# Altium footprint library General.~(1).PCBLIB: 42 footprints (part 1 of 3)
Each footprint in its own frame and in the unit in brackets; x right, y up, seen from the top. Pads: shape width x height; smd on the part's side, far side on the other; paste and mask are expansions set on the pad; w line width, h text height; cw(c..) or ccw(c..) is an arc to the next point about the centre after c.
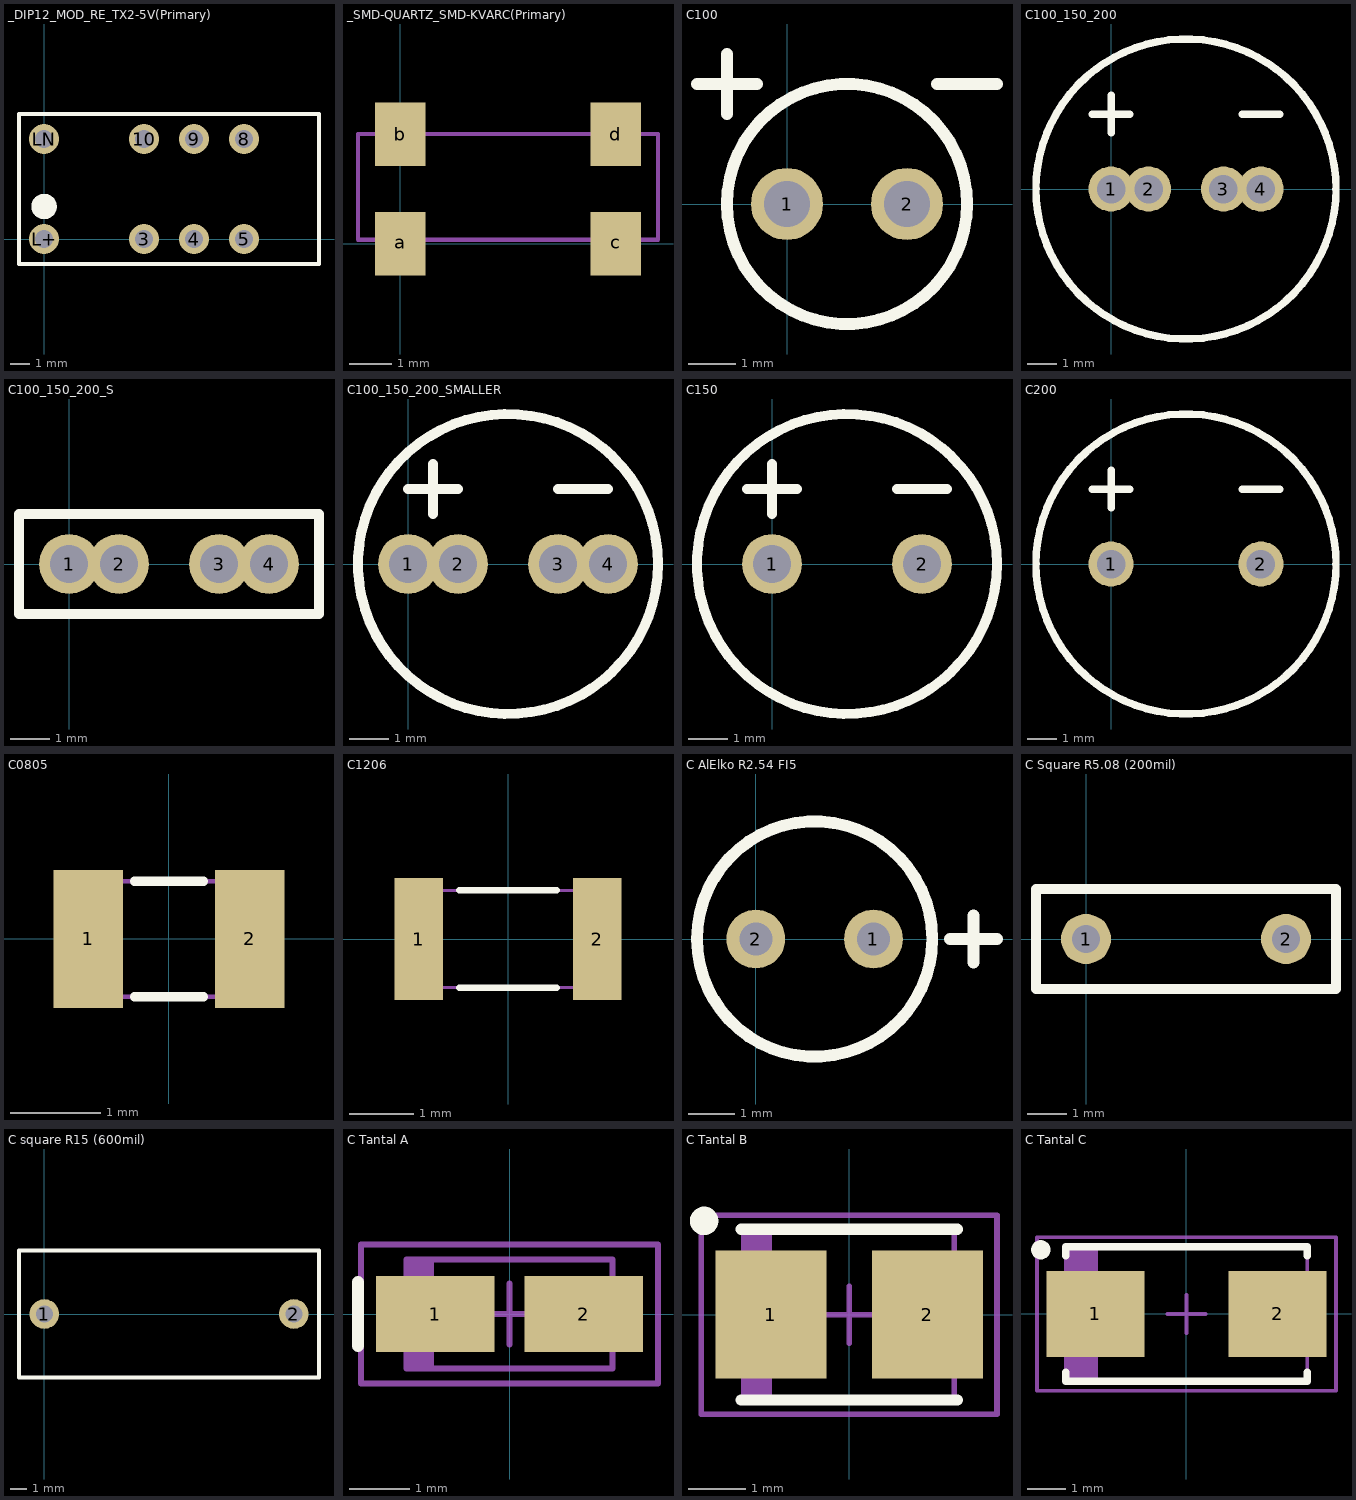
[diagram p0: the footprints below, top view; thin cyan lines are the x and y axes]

## _DIP12_MOD_RE_TX2-5V(Primary) [mil]
pads (8):
  round 60 hole 36: 3(200,0) 4(300,0) 5(400,0) 8(400,200) 9(300,200) 10(200,200) L+(0,0) LN(0,200)
Top Overlay:
  circle w25: c0,65 r13
  lines w8: -50,-50 -50,250 550,250 550,-50 -50,-50

## _SMD-QUARTZ_SMD-KVARC(Primary) [mm]
pads (4):
  rect 1.2x1.5 smd: a(0,0) b(0,2.6) c(5.1,0) d(5.1,2.6)
Mechanical 1:
  lines w0.1: -1,0.1 6.1,0.1 6.1,2.6 -1,2.6 -1,0.1

## C100 [mil]
pads (2):
  round 60 hole 38: 1(0,0) 2(100,0)
Top Overlay:
  circle w10: c50,0 r100
  lines w10: -75,100 -25,100 ; -50,75 -50,125 ; 125,100 175,100

## C100_150_200 [mil]
pads (4):
  round 60 hole 38: 1(0,0) 2(50,0) 3(150,0) 4(200,0)
Top Overlay:
  circle w10: c100,0 r200
  lines w10: -25,100 25,100 ; 0,75 0,125 ; 175,100 225,100

## C100_150_200_S [mil]
pads (4):
  round 60 hole 38: 1(0,0) 2(50,0) 3(150,0) 4(200,0)
Top Overlay:
  lines w10: -50,-50 -50,50 250,50 250,-50 -50,-50

## C100_150_200_SMALLER [mil]
pads (4):
  round 60 hole 38: 1(0,0) 2(50,0) 3(150,0) 4(200,0)
Top Overlay:
  circle w10: c100,0 r150
  lines w10: 0,75 50,75 ; 25,50 25,100 ; 150,75 200,75

## C150 [mil]
pads (2):
  round 60 hole 38: 1(0,0) 2(150,0)
Top Overlay:
  circle w10: c75,0 r150
  lines w10: -25,75 25,75 ; 0,50 0,100 ; 125,75 175,75

## C200 [mil]
pads (2):
  round 60 hole 38: 1(0,0) 2(200,0)
Top Overlay:
  circle w10: c100,0 r200
  lines w10: -25,100 25,100 ; 0,75 0,125 ; 175,100 225,100

## C0805 [mil]
pads (2):
  rect 30x60 smd: 1(-35,0) 2(35,0)
Top Overlay:
  lines w4: -15,-25 15,-25 ; -15,25 15,25
Mechanical 1:
  lines w1.97: -40,-25 -40,25 ; 40,-25 40,25
  lines w2: -40,-25 40,-25 ; -40,25 40,25
3D body "User Library-0805 SMD Capacitor.step": height 31.39, standoff 0.6, extent -39.37,-25 39.37,24.21

## C1206 [mil]
pads (2):
  rect 30x75 smd: 1(-55,0) 2(55,0)
Top Overlay:
  lines w4: -30,-30 30,-30 ; -30,30 30,30
Mechanical 1:
  lines w1.97: -60,-30 -60,30 60,30 60,-30 -60,-30
3D body "User Library-1206 SMD Resistor.step": height 40.05, standoff 0.6, extent -62.99,-31.99 62.99,31

## C AlElko R2.54 FI5 [mil]
height 393.7
pads (2):
  round 50 hole 28: 1(100,0) 2(0,0)
Top Overlay:
  circle w10: c50,0 r100
  lines w10: 165,0 205,0 ; 185,-20 185,20
3D body "User Library-Cap electro 6_3x7x2_5mm.step": height 110.8, standoff -304.15, extent -75.01,-125 175.02,125.02

## C Square R5.08 (200mil) [mil]
height 236.22
pads (2):
  round 50 hole 28: 1(0,0) 2(200,0)
Top Overlay:
  lines w10: -50,-50 250,-50 250,50 -50,50 -50,-50
3D body "User Library-100n.step": height 299.21, standoff -181.1, extent -47.64,-49.21 247.64,49.21

## C square R15 (600mil) [mil]
height 590.55
pads (2):
  round 70 hole 40: 1(0,0) 2(590.55,0)
Top Overlay:
  lines w10: -60,-150 -60,150 650,150 650,-150 -60,-150
3D body "User Library-cap_r60_pi3100d0j.step": height 532.1, standoff -688.37, extent -58.66,-147.64 650,147.64

## C Tantal A [mm] "Molded Capacitor, 2-Leads, Body 3,2x1,6mm, IPC Medium Density"
height 1.8
pads (2):
  rect 1.95x1.25 smd: 1(-1.225,0) 2(1.225,0)
Top Overlay:
  lines w0.2: -2.5,-0.525 -2.5,0.525
Mechanical 13:
  rectangle: -1.7,-0.9 -1.243,0.9
  lines w0.1: -1.7,-0.9 -1.7,0.9 1.7,0.9 1.7,-0.9 -1.7,-0.9
Mechanical 15:
  lines w0.1: -0.5,0 0.5,0 ; 0,-0.5 0,0.5 ; -2.45,-1.15 -2.45,1.15 2.45,1.15 2.45,-1.15 -2.45,-1.15
3D body "User Library-cap_a.step": height 1.63, standoff 0.02, extent -1.595,-0.813 1.595,0.787

## C Tantal B [mm] "Molded Capacitor, 2-Leads, Body 3,5x2,8mm, IPC Medium Density"
height 2.1
pads (2):
  rect 1.95x2.25 smd: 1(-1.375,0) 2(1.375,0)
Top Overlay:
  circle w0.25: c-2.55,1.65 r0.125
  lines w0.2: -1.9,-1.5 1.9,-1.5 ; -1.9,1.5 1.9,1.5
Mechanical 13:
  rectangle: -1.85,-1.5 -1.352,1.5
  lines w0.1: -1.85,-1.5 -1.85,1.5 1.85,1.5 1.85,-1.5 -1.85,-1.5
Mechanical 15:
  lines w0.1: -0.5,0 0.5,0 ; 0,-0.5 0,0.5 ; -2.6,-1.75 -2.6,1.75 2.6,1.75 2.6,-1.75 -2.6,-1.75
3D body "User Library-cap_b.step": height 1.93, standoff 0.02, extent -1.695,-1.397 1.797,1.403

## C Tantal C [mm] "Molded Capacitor, 2-Leads, Body 6,0x3,2mm, IPC Medium Density"
height 2.8
pads (2):
  rect 2.55x2.25 smd: 1(-2.375,0) 2(2.375,0)
Top Overlay:
  circle w0.25: c-3.8,1.675 r0.125
  lines w0.2: -3.15,-1.525 -3.15,-1.75 3.15,-1.75 3.15,-1.525 ; -3.15,1.525 -3.15,1.75 3.15,1.75 3.15,1.525
Mechanical 13:
  rectangle: -3.15,-1.75 -2.303,1.75
  lines w0.1: -3.15,-1.75 -3.15,1.75 3.15,1.75 3.15,-1.75 -3.15,-1.75
Mechanical 15:
  lines w0.1: -0.5,0 0.5,0 ; 0,-0.5 0,0.5 ; -3.9,-2 -3.9,2 3.9,2 3.9,-2 -3.9,-2
3D body "User Library-cap_c.step": height 2.53, standoff 0.02, extent -2.972,-1.6 3.022,1.6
